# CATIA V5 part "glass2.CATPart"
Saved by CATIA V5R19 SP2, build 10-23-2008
Part number: glass2
Bounding box of the stored display mesh (mm): x -1092.449 to 1304.562, y -666.45 to 666.45, z 591.294 to 1005.829
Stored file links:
  C:\BEHROOZ\catia learning\tarh haye mashin\hb\glass2.CATPart
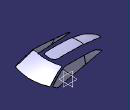
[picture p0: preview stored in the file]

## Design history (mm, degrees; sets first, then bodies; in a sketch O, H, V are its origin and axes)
Body1 (main body)
  DatumSurface1
  ThickSurface1: Surface DatumSurface1, TopOffset 5, BotOffset -4
  DatumSurface2
  ThickSurface2: Surface DatumSurface2, TopOffset 5, BotOffset -4
  DatumSurface3
  ThickSurface3: Surface DatumSurface3, TopOffset 5, BotOffset -4
  DatumSurface4
  Plane1: stored without definition
  ThickSurface4: Surface DatumSurface4, TopOffset 5, BotOffset -4
  DatumCurve1
  Sketch1, origin (0, 0, 449), H (1, 0, 0), V (0, 1, 0), geometry linked from another document
  Sketch2 on Plane1, origin (0, 750, 0), H (-1, 0, 0), V (0, 0, 1)
    projected arc E1 centre (-4224.9857, 1613.9741) radius 4330.792 from (-6.9407, 632.2123) to (14.261, 728.2274) ccw from edge of DatumCurve1
    projected arc E2 centre (-4224.9857, 1613.9741) radius 4330.792 from (-6.9407, 632.2123) to (52.7224, 937.976) ccw from edge of DatumCurve1
  Pocket1: profile Sketch2, direction (0, -1, 0), length 2743, thin wall 1
  Pocket2: profile Sketch1, direction (0, 0, 1), length 2743, thin wall 1
  DatumSurface5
